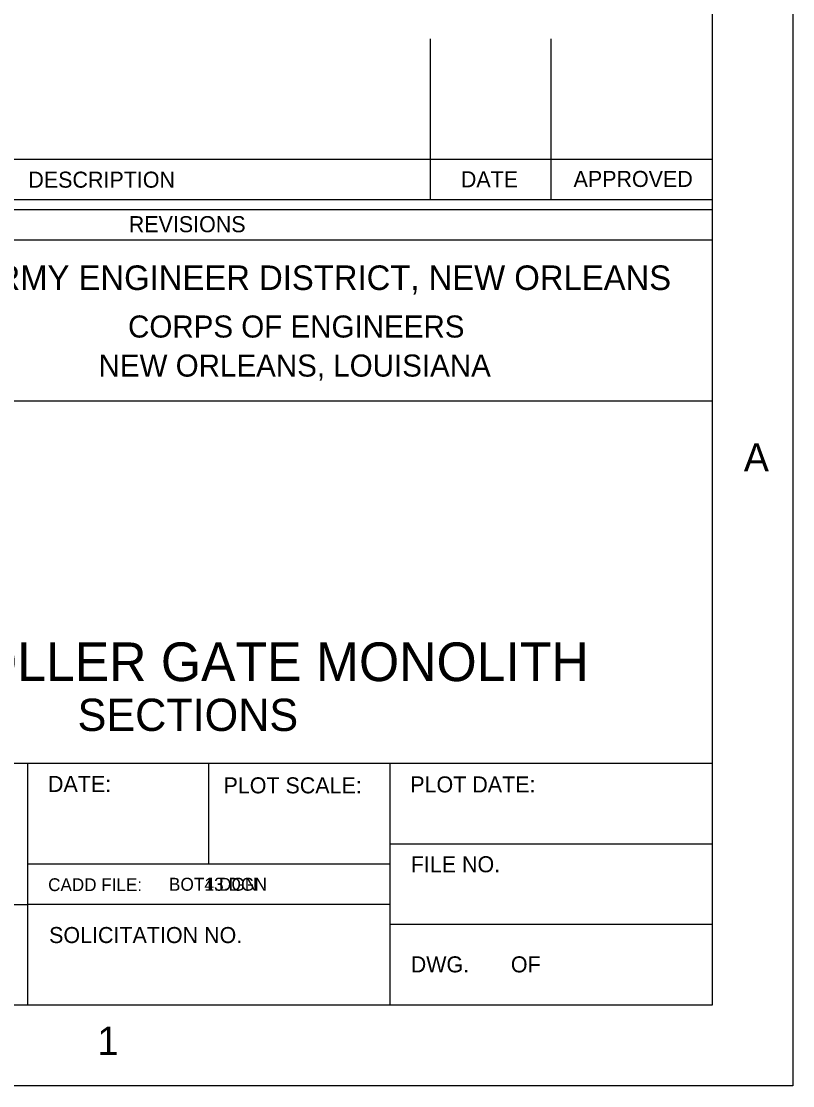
# Model space of a CAD drawing. Extents: x 0 to 320, y -4 to 473.
# Drawn here: x 35.21 to 40, y 0 to 6.61 of the extents above; entities that cross this region are included whole.
import ezdxf

# ---------------------------------------------------------------- set-up
doc = ezdxf.new("R2010")
doc.units = 0
doc.layers.add('Level 1', color=7, linetype='Continuous')
doc.layers.add('Level 2', color=7, linetype='Continuous')

msp = doc.modelspace()

# ---------------------------------------------------------------- linework, layer by layer
at = {"layer": 'Level 1'}
for p, q in [((37.75, 5.5), (37.75, 6.5)), ((38.5, 5.5), (38.5, 6.5)), ((39.5, 5.75), (33, 5.75)), ((39.5, 5.5), (33, 5.5)), ((39.5, 5.4375), (33, 5.4375)), ((39.5, 5.25), (33, 5.25)), ((39.5, 4.25), (33, 4.25)), ((39.5, 2), (33, 2)), ((35.25, 0.5), (35.25, 2)), ((36.375, 1.375), (36.375, 2)), ((37.5, 0.5), (37.5, 2)), ((39.5, 1.5), (37.5, 1.5)), ((37.5, 1.375), (35.25, 1.375)), ((33, 1.125), (35.25, 1.125)), ((37.5, 1.125), (35.25, 1.125)), ((39.5, 1), (37.5, 1))]:
    msp.add_line(p, q, dxfattribs=at)
for points in [[(0, 28), (40, 28), (40, 0), (0, 0)], [(1.5, 27.5), (39.5, 27.5), (39.5, 0.5), (1.5, 0.5)]]:
    msp.add_lwpolyline(points, close=True, dxfattribs=at)

# ---------------------------------------------------------------- texts
for s, height, p in [('DESCRIPTION', 0.099625, (35.254, 5.5754)), ('DATE', 0.09962, (37.9395, 5.5778)), ('APPROVED', 0.09962, (38.6393, 5.5799)), ('REVISIONS', 0.09962, (35.8774, 5.299)), ('U.S. ARMY ENGINEER DISTRICT, NEW ORLEANS', 0.152375, (34.4674, 4.9403)), ('CORPS OF ENGINEERS', 0.137138, (35.873, 4.6449)), ('NEW ORLEANS, LOUISIANA', 0.137138, (35.69, 4.4025)), ('A', 0.1753, (39.6963, 3.8134)), ('DATE:', 0.09962, (35.3759, 1.8238)), ('PLOT DATE:', 0.09962, (37.6255, 1.8208)), ('PLOT SCALE:', 0.099625, (36.4656, 1.815)), ('FILE NO.', 0.09962, (37.6283, 1.3251)), ('CADD FILE:', 0.07925, (35.3769, 1.2085)), ('SOLICITATION NO.', 0.099625, (35.3828, 0.8856)), ('DWG.       OF', 0.099625, (37.6283, 0.7036)), ('1', 0.1753, (35.6825, 0.1911))]:
    msp.add_text(s, height=height, dxfattribs=at).set_placement(p)
at = {"layer": 'Level 2'}
for s, height, p in [('BOTTOM ROLLER GATE MONOLITH', 0.23999, (33.2415, 2.512)), ('SECTIONS', 0.20036, (35.5597, 2.2025)), ('BOT4.DGN', 0.08038, (36.1263, 1.2105)), ('BOT13.DGN', 0.08038, (36.1263, 1.2105))]:
    msp.add_text(s, height=height, dxfattribs=at).set_placement(p)

doc.saveas('drawing.dxf')
